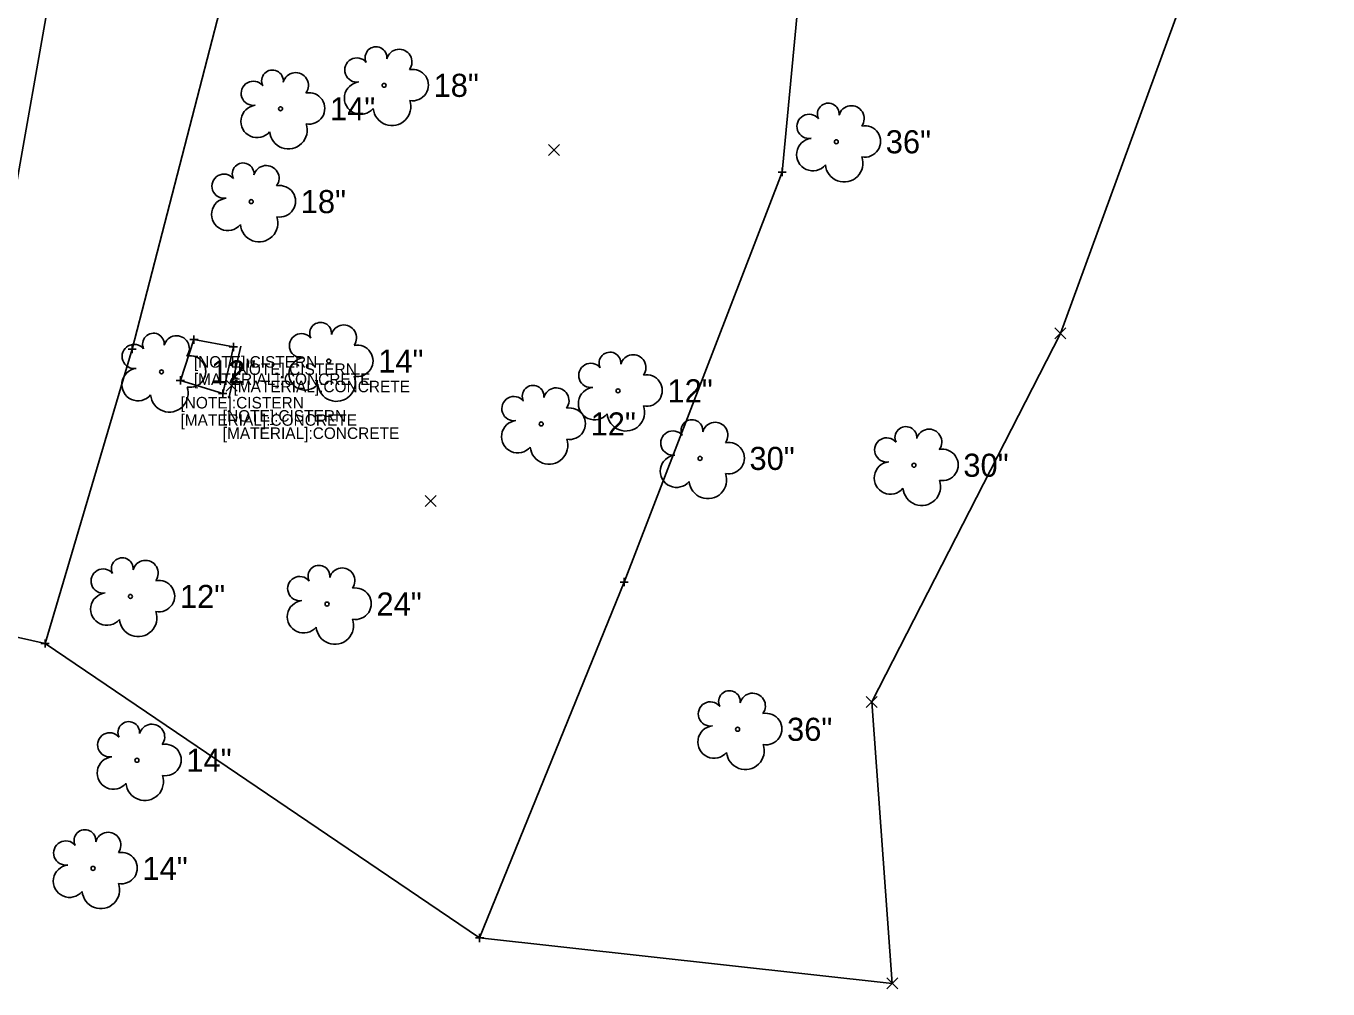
# Model space of a CAD drawing. Extents: x 1380627 to 1381920, y 503402 to 506786.
# Drawn here: x 1381754.6 to 1381912.7, y 504551.3 to 504668.1 of the extents above; entities that cross this region are included whole.
import ezdxf

# ---------------------------------------------------------------- set-up
doc = ezdxf.new("R2010")
doc.units = 0
for name, color, linetype in [('RD_X_Concrete_Pad', 7, 'Continuous'), ('SV_X_Original_Ground', 7, 'Continuous'), ('SV_X_Random_Point', 7, 'Continuous'), ('SV_X_Shot_Marker', 7, 'Continuous'), ('SV_X_Terrain_Boundary', 7, 'Continuous'), ('SV_X_Text', 7, 'Continuous'), ('SV_X_Toe_of_Slope', 7, 'Continuous'), ('SV_X_Top_of_Bank', 7, 'Continuous'), ('VG_X_Cells', 7, 'Continuous'), ('VG_X_Text', 7, 'Continuous')]:
    doc.layers.add(name, color=color, linetype=linetype)

msp = doc.modelspace()

# ---------------------------------------------------------------- linework, layer by layer
at = {"layer": 'RD_X_Concrete_Pad'}
msp.add_lwpolyline([(1381773.39, 504625.11), (1381775.02, 504630.06), (1381779.82, 504629.18), (1381778.52, 504623.51)], close=True, dxfattribs=at)
at = {"layer": 'SV_X_Original_Ground'}
msp.add_line((1381779.25, 504622.96), (1381780.73, 504629.28), dxfattribs=at)
at = {"layer": 'SV_X_Random_Point'}
for p, q in [((1381818.07, 504652.42), (1381819.41, 504653.75)), ((1381818.07, 504653.75), (1381819.41, 504652.42)), ((1381879.51, 504630.16), (1381880.85, 504631.49)), ((1381879.51, 504631.49), (1381880.85, 504630.16)), ((1381778.94, 504623.82), (1381780.27, 504625.15)), ((1381778.94, 504625.15), (1381780.27, 504623.82)), ((1381803.08, 504609.82), (1381804.42, 504611.15)), ((1381803.08, 504611.15), (1381804.42, 504609.82)), ((1381856.63, 504585.43), (1381857.96, 504586.77)), ((1381856.63, 504586.77), (1381857.96, 504585.43)), ((1381859.12, 504551.27), (1381860.45, 504552.61)), ((1381859.12, 504552.61), (1381860.45, 504551.27))]:
    msp.add_line(p, q, dxfattribs=at)
at = {"layer": 'SV_X_Shot_Marker'}
for p, q in [((1381846.42, 504650.9), (1381846.42, 504649.9)), ((1381845.92, 504650.4), (1381846.92, 504650.4)), ((1381846.42, 504650.4), (1381846.42, 504650.4)), ((1381775.02, 504630.56), (1381775.02, 504629.56)), ((1381767.03, 504628.92), (1381768.03, 504628.92)), ((1381767.53, 504629.42), (1381767.53, 504628.42)), ((1381767.53, 504628.92), (1381767.53, 504628.92)), ((1381774.52, 504630.06), (1381775.52, 504630.06)), ((1381775.02, 504630.06), (1381775.02, 504630.06)), ((1381779.32, 504629.18), (1381780.32, 504629.18)), ((1381779.82, 504629.68), (1381779.82, 504628.68)), ((1381779.82, 504629.18), (1381779.82, 504629.18)), ((1381773.39, 504625.61), (1381773.39, 504624.61)), ((1381772.89, 504625.11), (1381773.89, 504625.11)), ((1381773.39, 504625.11), (1381773.39, 504625.11)), ((1381778.52, 504624.01), (1381778.52, 504623.01)), ((1381778.02, 504623.51), (1381779.02, 504623.51)), ((1381778.52, 504623.51), (1381778.52, 504623.51)), ((1381826.74, 504600.65), (1381827.74, 504600.65)), ((1381827.24, 504601.15), (1381827.24, 504600.15)), ((1381827.24, 504600.65), (1381827.24, 504600.65)), ((1381756.46, 504593.19), (1381757.46, 504593.19)), ((1381756.96, 504593.69), (1381756.96, 504592.69)), ((1381756.96, 504593.19), (1381756.96, 504593.19)), ((1381809.2, 504557.46), (1381810.2, 504557.46)), ((1381809.7, 504557.96), (1381809.7, 504556.96)), ((1381809.7, 504557.46), (1381809.7, 504557.46))]:
    msp.add_line(p, q, dxfattribs=at)
at = {"layer": 'SV_X_Terrain_Boundary'}
msp.add_lwpolyline([(1381633.07, 504590.71), (1381640.41, 504588.23), (1381652.11, 504583.89), (1381663.49, 504580.19), (1381671.46, 504576.88), (1381673.04, 504575.38), (1381691.74, 504593.89), (1381728.42, 504597.15), (1381743.97, 504596.11), (1381756.96, 504593.19), (1381809.7, 504557.46), (1381859.78, 504551.94), (1381857.29, 504586.1), (1381880.18, 504630.82), (1381903.11, 504693.5), (1381902.57, 504736.65), (1381902.08, 504783.53), (1381912.66, 504838.51)], dxfattribs=at)
at = {"layer": 'SV_X_Toe_of_Slope'}
for points in [[(1381809.7, 504557.46), (1381827.24, 504600.65), (1381846.42, 504650.4), (1381850.64, 504694.87), (1381860.29, 504748.65), (1381866.47, 504788.59), (1381874.56, 504846.72), (1381883.38, 504901.17)], [(1381743.97, 504596.11), (1381750.58, 504632.7), (1381758.24, 504675.79), (1381761.89, 504691.85)]]:
    msp.add_lwpolyline(points, dxfattribs=at)
at = {"layer": 'SV_X_Top_of_Bank'}
msp.add_lwpolyline([(1381756.96, 504593.19), (1381767.53, 504628.92), (1381778.46, 504671.13), (1381783.31, 504685.95), (1381763.75, 504690.91)], dxfattribs=at)
at = {"layer": 'VG_X_Cells'}
for centre in [(1381798.11, 504660.92), (1381785.54, 504658.08), (1381852.99, 504654.07), (1381781.98, 504646.81), (1381791.39, 504627.46), (1381771.09, 504626.15), (1381826.5, 504623.85), (1381817.17, 504619.83), (1381836.45, 504615.65), (1381862.41, 504614.82), (1381767.32, 504598.9), (1381791.18, 504597.98), (1381841.01, 504582.78), (1381768.11, 504579.02), (1381762.78, 504565.9)]:
    msp.add_circle(centre, 0.24, dxfattribs=at)
for centre, radius, start, end in [((1381797.13, 504664.28), 1.32, 354.0047, 205.9741), ((1381799.94, 504663.75), 1.55, 323.83, 165.0376), ((1381794.8, 504662.78), 1.47, 39.0625, 279.5412), ((1381784.56, 504661.45), 1.32, 354.0047, 205.9741), ((1381787.37, 504660.91), 1.55, 323.83, 165.0376), ((1381801.57, 504660.95), 1.91, 259.1453, 101.4596), ((1381782.23, 504659.95), 1.47, 39.0625, 279.5412), ((1381795.26, 504659.37), 1.97, 96.1722, 320.5737), ((1381789, 504658.12), 1.91, 259.1453, 101.4596), ((1381799.06, 504658.31), 2.28, 184.9476, 19.4572), ((1381852.01, 504657.44), 1.32, 354.0047, 205.9741), ((1381782.69, 504656.54), 1.97, 96.1722, 320.5737), ((1381849.68, 504655.94), 1.47, 39.0625, 279.5412), ((1381854.82, 504656.9), 1.55, 323.83, 165.0376), ((1381786.49, 504655.48), 2.28, 184.9476, 19.4572), ((1381856.45, 504654.11), 1.91, 259.1453, 101.4596), ((1381850.14, 504652.52), 1.97, 96.1722, 320.5737), ((1381781, 504650.18), 1.32, 354.0047, 205.9741), ((1381783.81, 504649.64), 1.55, 323.83, 165.0376), ((1381853.94, 504651.47), 2.28, 184.9476, 19.4572), ((1381778.68, 504648.68), 1.47, 39.0625, 279.5412), ((1381785.45, 504646.85), 1.91, 259.1453, 101.4596), ((1381779.13, 504645.26), 1.97, 96.1722, 320.5737), ((1381782.93, 504644.21), 2.28, 184.9476, 19.4572), ((1381790.4, 504630.83), 1.32, 354.0047, 205.9741), ((1381793.21, 504630.29), 1.55, 323.83, 165.0376), ((1381770.11, 504629.52), 1.32, 354.0047, 205.9741), ((1381772.92, 504628.98), 1.55, 323.83, 165.0376), ((1381788.08, 504629.32), 1.47, 39.0625, 279.5412), ((1381767.78, 504628.02), 1.47, 39.0625, 279.5412), ((1381794.85, 504627.49), 1.91, 259.1453, 101.4596), ((1381774.55, 504626.19), 1.91, 259.1453, 101.4596), ((1381788.53, 504625.91), 1.97, 96.1722, 320.5737), ((1381823.19, 504625.72), 1.47, 39.0625, 279.5412), ((1381825.52, 504627.22), 1.32, 354.0047, 205.9741), ((1381828.33, 504626.68), 1.55, 323.83, 165.0376), ((1381768.24, 504624.61), 1.97, 96.1722, 320.5737), ((1381792.33, 504624.85), 2.28, 184.9476, 19.4572), ((1381829.96, 504623.89), 1.91, 259.1453, 101.4596), ((1381772.04, 504623.55), 2.28, 184.9476, 19.4572), ((1381816.19, 504623.19), 1.32, 354.0047, 205.9741), ((1381819, 504622.66), 1.55, 323.83, 165.0376), ((1381823.65, 504622.3), 1.97, 96.1722, 320.5737), ((1381813.86, 504621.69), 1.47, 39.0625, 279.5412), ((1381820.63, 504619.86), 1.91, 259.1453, 101.4596), ((1381827.45, 504621.25), 2.28, 184.9476, 19.4572), ((1381814.32, 504618.28), 1.97, 96.1722, 320.5737), ((1381835.47, 504619.02), 1.32, 354.0047, 205.9741), ((1381838.28, 504618.48), 1.55, 323.83, 165.0376), ((1381861.43, 504618.19), 1.32, 354.0047, 205.9741), ((1381864.24, 504617.65), 1.55, 323.83, 165.0376), ((1381818.12, 504617.22), 2.28, 184.9476, 19.4572), ((1381833.15, 504617.51), 1.47, 39.0625, 279.5412), ((1381839.92, 504615.68), 1.91, 259.1453, 101.4596), ((1381859.1, 504616.68), 1.47, 39.0625, 279.5412), ((1381833.6, 504614.1), 1.97, 96.1722, 320.5737), ((1381865.87, 504614.86), 1.91, 259.1453, 101.4596), ((1381859.56, 504613.27), 1.97, 96.1722, 320.5737), ((1381837.4, 504613.04), 2.28, 184.9476, 19.4572), ((1381863.36, 504612.21), 2.28, 184.9476, 19.4572), ((1381766.33, 504602.27), 1.32, 354.0047, 205.9741), ((1381769.14, 504601.73), 1.55, 323.83, 165.0376), ((1381764.01, 504600.77), 1.47, 39.0625, 279.5412), ((1381790.2, 504601.35), 1.32, 354.0047, 205.9741), ((1381793.01, 504600.81), 1.55, 323.83, 165.0376), ((1381770.78, 504598.94), 1.91, 259.1453, 101.4596), ((1381787.87, 504599.85), 1.47, 39.0625, 279.5412), ((1381764.46, 504597.36), 1.97, 96.1722, 320.5737), ((1381794.64, 504598.02), 1.91, 259.1453, 101.4596), ((1381768.26, 504596.3), 2.28, 184.9476, 19.4572), ((1381788.33, 504596.43), 1.97, 96.1722, 320.5737), ((1381792.13, 504595.38), 2.28, 184.9476, 19.4572), ((1381840.02, 504586.14), 1.32, 354.0047, 205.9741), ((1381837.7, 504584.64), 1.47, 39.0625, 279.5412), ((1381842.83, 504585.61), 1.55, 323.83, 165.0376), ((1381844.47, 504582.81), 1.91, 259.1453, 101.4596), ((1381767.12, 504582.39), 1.32, 354.0047, 205.9741), ((1381769.93, 504581.85), 1.55, 323.83, 165.0376), ((1381838.15, 504581.23), 1.97, 96.1722, 320.5737), ((1381764.8, 504580.89), 1.47, 39.0625, 279.5412), ((1381771.57, 504579.06), 1.91, 259.1453, 101.4596), ((1381841.95, 504580.17), 2.28, 184.9476, 19.4572), ((1381765.25, 504577.47), 1.97, 96.1722, 320.5737), ((1381769.05, 504576.42), 2.28, 184.9476, 19.4572), ((1381761.8, 504569.27), 1.32, 354.0047, 205.9741), ((1381764.61, 504568.73), 1.55, 323.83, 165.0376), ((1381759.47, 504567.77), 1.47, 39.0625, 279.5412), ((1381766.24, 504565.94), 1.91, 259.1453, 101.4596), ((1381759.93, 504564.35), 1.97, 96.1722, 320.5737), ((1381763.73, 504563.3), 2.28, 184.9476, 19.4572)]:
    msp.add_arc(centre, radius, start, end, dxfattribs=at)

# ---------------------------------------------------------------- texts
at = {"layer": 'SV_X_Text'}
for s, p in [('[NOTE]:CISTERN', (1381775.02, 504626.66)), ('[NOTE]:CISTERN', (1381779.82, 504625.78)), ('[MATERIAL]:CONCRETE', (1381775.02, 504624.56)), ('[MATERIAL]:CONCRETE', (1381779.82, 504623.68)), ('[NOTE]:CISTERN', (1381773.39, 504621.71)), ('[MATERIAL]:CONCRETE', (1381773.39, 504619.61)), ('[NOTE]:CISTERN', (1381778.52, 504620.11)), ('[MATERIAL]:CONCRETE', (1381778.52, 504618.01))]:
    msp.add_text(s, height=1.4, dxfattribs=at).set_placement(p)
at = {"layer": 'VG_X_Text'}
for s, p in [('18"', (1381804.11, 504659.52)), ('14"', (1381791.54, 504656.68)), ('36"', (1381858.99, 504652.67)), ('18"', (1381787.99, 504645.41)), ('14"', (1381797.39, 504626.06)), ('12"', (1381777.09, 504624.75)), ('12"', (1381832.5, 504622.45)), ('12"', (1381823.17, 504618.43)), ('30"', (1381842.45, 504614.25)), ('30"', (1381868.41, 504613.42)), ('12"', (1381773.32, 504597.5)), ('24"', (1381797.18, 504596.58)), ('36"', (1381847.01, 504581.38)), ('14"', (1381774.11, 504577.62)), ('14"', (1381768.78, 504564.5))]:
    msp.add_text(s, height=2.8, dxfattribs=at).set_placement(p)

doc.saveas('drawing.dxf')
